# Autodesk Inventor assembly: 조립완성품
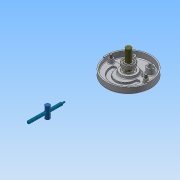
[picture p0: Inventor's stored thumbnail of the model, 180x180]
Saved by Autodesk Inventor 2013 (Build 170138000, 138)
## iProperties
Created: 2015-06
Part Number: 조립완성품
Document SubType Name: Assembly
Designer: Administrator
Author: Administrator
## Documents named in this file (10)
- C:\Documents and Settings\Administrator\바탕 화면\450631V1024\조립완성품.iam
- C:\Documents and Settings\Administrator\바탕 화면\450631V1024\본체.ipt
- C:\Documents and Settings\Administrator\바탕 화면\450631V1024\덮개.ipt
- C:\Documents and Settings\Administrator\바탕 화면\450631V1024\축.ipt
- C:\Documents and Settings\Administrator\바탕 화면\450631V1024\베어링62_22.ipt
- C:\Documents and Settings\Administrator\바탕 화면\450631V1024\슬라이더.ipt
- C:\Documents and Settings\Administrator\바탕 화면\450631V1024\평행핀.ipt
- C:\Documents and Settings\Administrator\바탕 화면\450631V1024\멈춤링.ipt
- C:\Documents and Settings\Administrator\바탕 화면\450631V1024\M10x35.ipt
- C:\Documents and Settings\Administrator\바탕 화면\450631V1024\슬라이더2.ipt
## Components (7 placed, 4 different names)
1. KS B 2023 62/22 - 22 x 50 x 14:1
2. KS B 2023 62/22 - 22 x 50 x 14:2
3. KS B 1336 22 x 1.2:1
4. KS B 1336 22 x 1.2:2
5. KS B 1003 - 미터 M 10 x 35:1
6. KS B 1003 - 미터 M 10 x 35:2
7. KS B 1320 B B 5 x  20:1 — 플러쉬:1
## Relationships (1: Flush 1)
- 플러쉬:1 [Flush]: KS B 1320 B B 5 x  20:1
